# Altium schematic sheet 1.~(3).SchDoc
size 420 x 297 mm
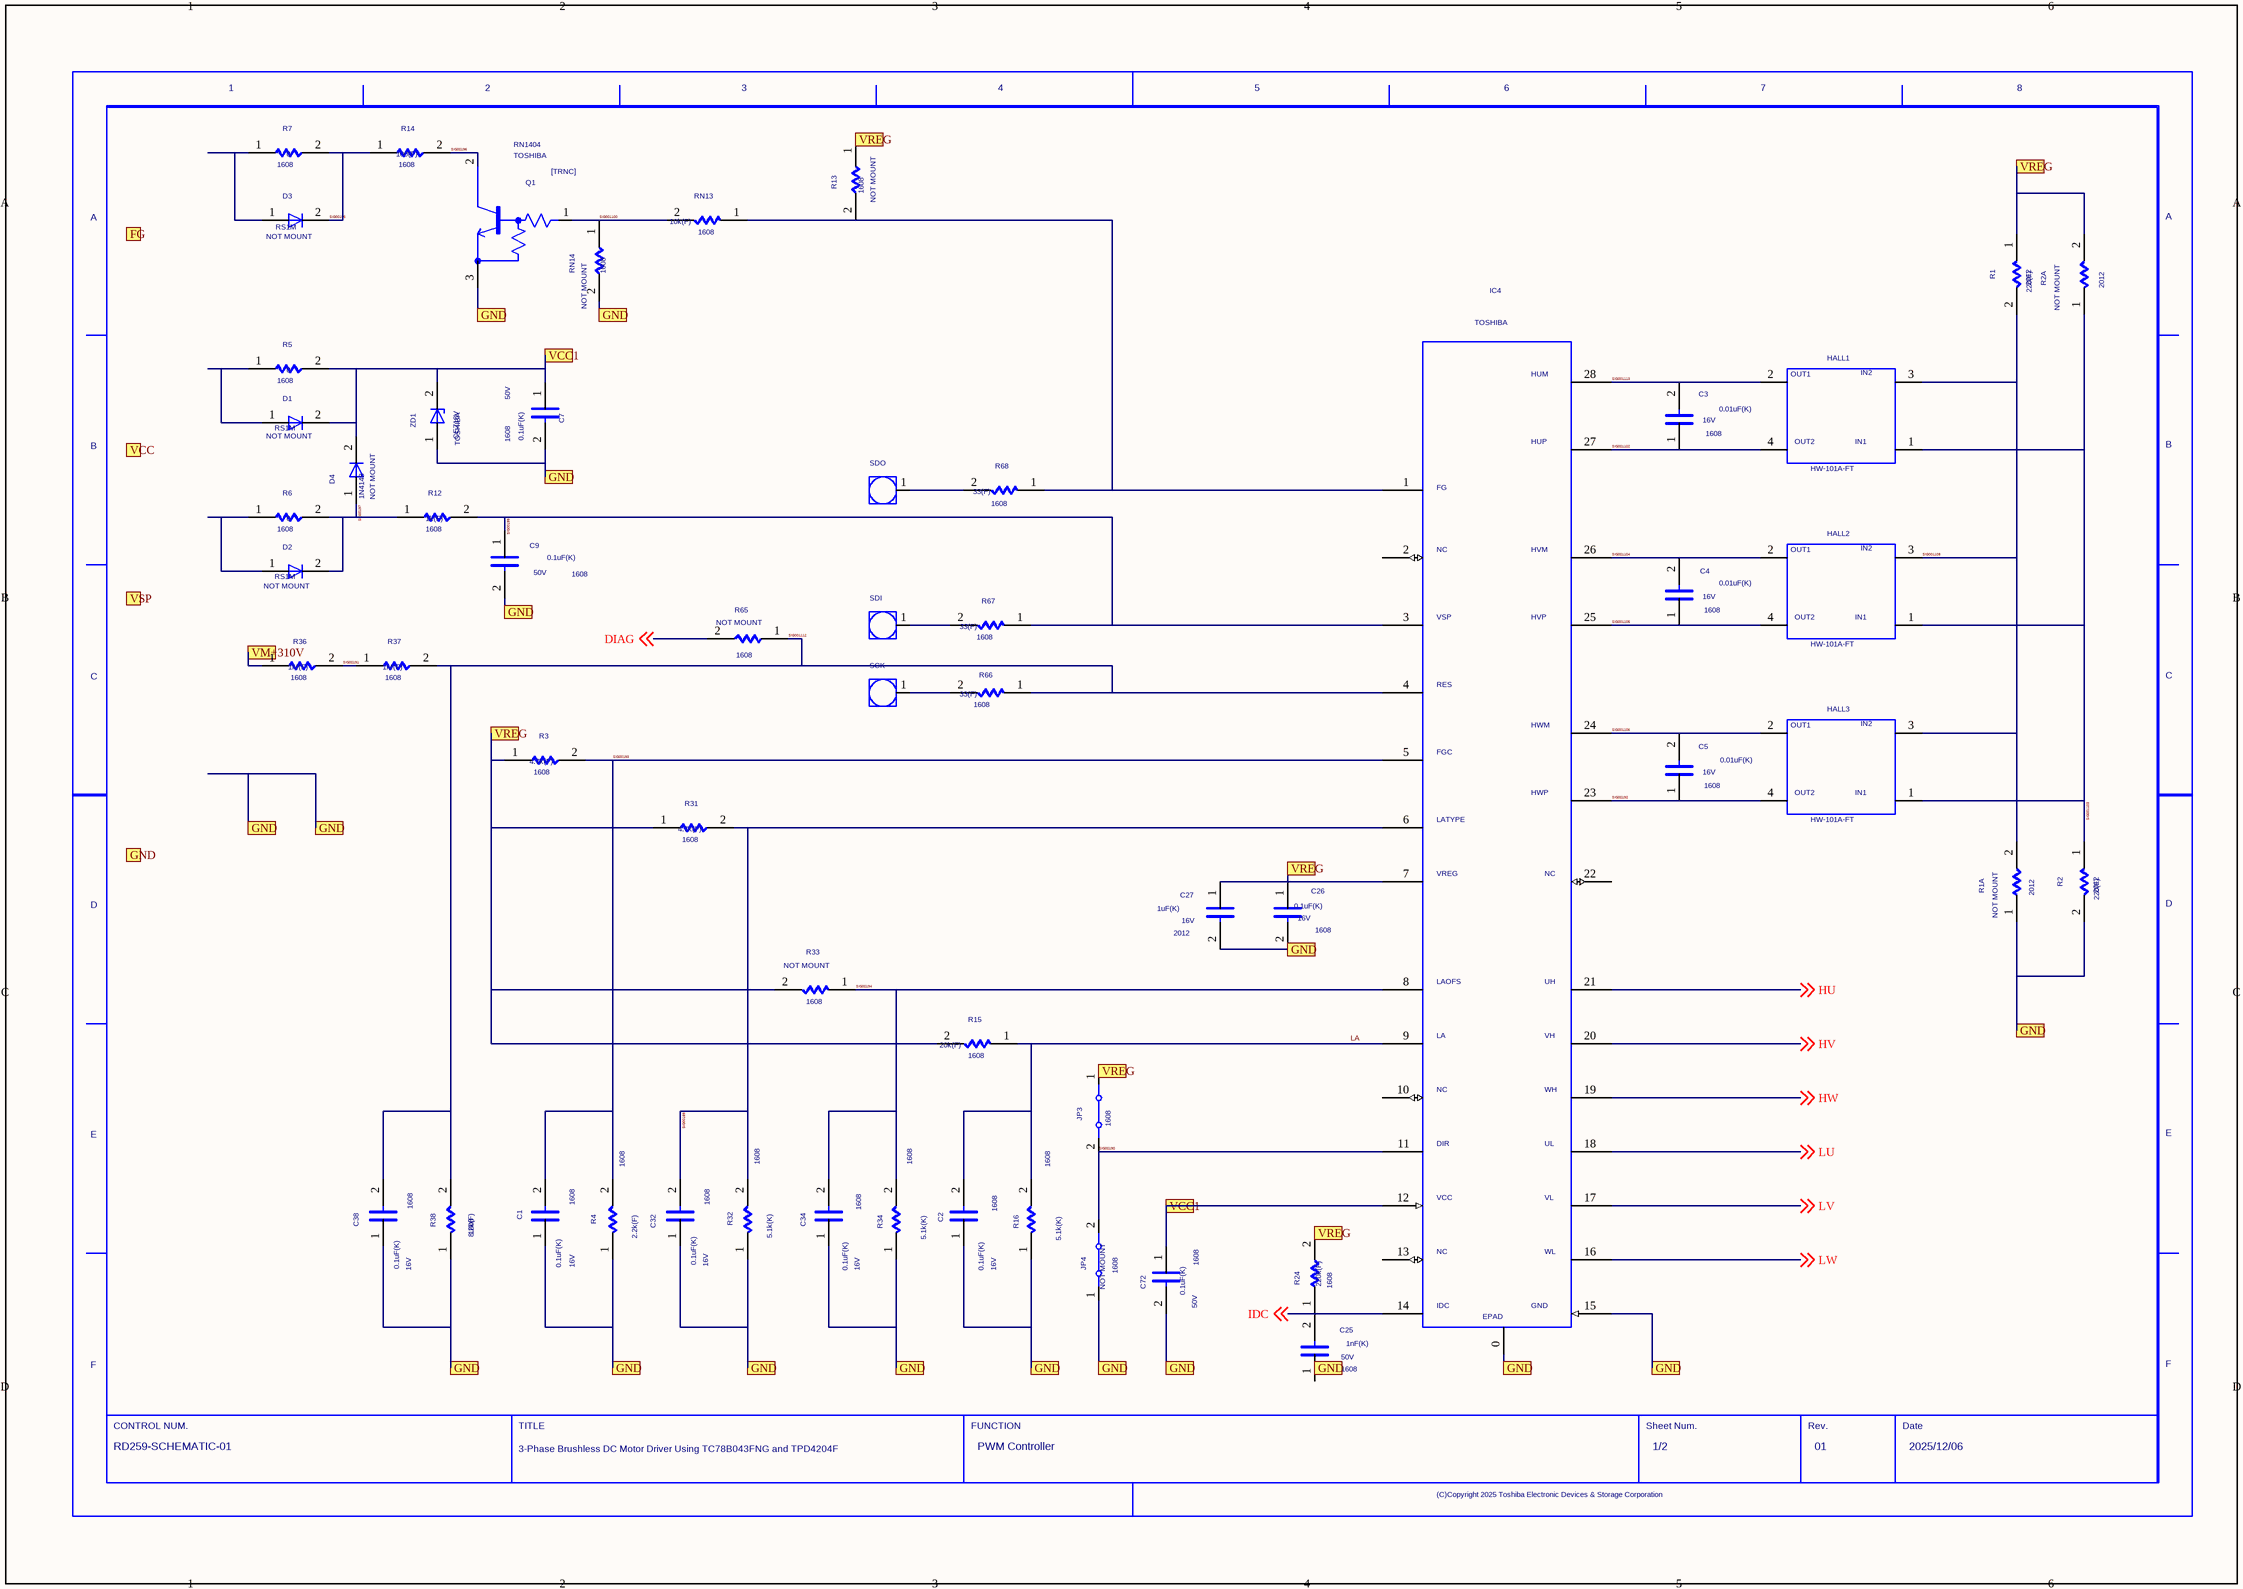
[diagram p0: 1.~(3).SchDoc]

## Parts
C1  VAL1: 0.1uF(K)  VAL2: 16V  SIZECODESMD: 1608  (hidden comment: C)
C2  VAL1: 0.1uF(K)  VAL2: 16V  SIZECODESMD: 1608  (hidden comment: C)
C3  VAL1: 0.01uF(K)  VAL2: 16V  SIZECODESMD: 1608  (hidden comment: C)
C4  VAL1: 0.01uF(K)  VAL2: 16V  SIZECODESMD: 1608  (hidden comment: C)
C5  VAL1: 0.01uF(K)  VAL2: 16V  SIZECODESMD: 1608  (hidden comment: C)
C7  VAL1: 0.1uF(K)  VAL2: 50V  SIZECODESMD: 1608  (hidden comment: C)
C9  VAL1: 0.1uF(K)  VAL2: 50V  SIZECODESMD: 1608  (hidden comment: C)
C25  VAL1: 1nF(K)  VAL2: 50V  SIZECODESMD: 1608  (hidden comment: C)
C26  VAL1: 0.1uF(K)  VAL2: 16V  SIZECODESMD: 1608  (hidden comment: C)
C27  VAL1: 1uF(K)  VAL2: 16V  SIZECODESMD: 2012  (hidden comment: C)
C32  VAL1: 0.1uF(K)  VAL2: 16V  SIZECODESMD: 1608  (hidden comment: C)
C34  VAL1: 0.1uF(K)  VAL2: 16V  SIZECODESMD: 1608  (hidden comment: C)
C38  VAL1: 0.1uF(K)  VAL2: 16V  SIZECODESMD: 1608  (hidden comment: C)
C72  VAL1: 0.1uF(K)  VAL2: 50V  SIZECODESMD: 1608  (hidden comment: C)
D1  VAL3: RS1M  NOTMNT: NOT MOUNT  (hidden comment: D)
D2  VAL3: RS1M  NOTMNT: NOT MOUNT  (hidden comment: D)
D3  NOTMNT: NOT MOUNT  VAL3: RS1M  (hidden comment: D)
D4  NOTMNT: NOT MOUNT  VAL3: 1N4148  (hidden comment: D)
HALL1  HW-101A-FT
HALL2  HW-101A-FT
HALL3  HW-101A-FT
IC4  USERCOMPTEXT3: TOSHIBA  (hidden comment: TC78B043FNG)
JP3  SIZECODESMD: 1608  (hidden comment: JP)
JP4  NOTMNT: NOT MOUNT  SIZECODESMD: 1608  (hidden comment: JP)
Q1  USERCOMPTEXT3: TOSHIBA  VAL3: RN1404  (hidden comment: TRNC)
R1  VAL1: 220(F)  SIZECODESMD: 2012  (hidden comment: R)
R1A  NOTMNT: NOT MOUNT  SIZECODESMD: 2012  (hidden comment: R)
R2  VAL1: 220(F)  SIZECODESMD: 2012  (hidden comment: R)
R2A  NOTMNT: NOT MOUNT  SIZECODESMD: 2012  (hidden comment: R)
R3  VAL1: 4.7k(F)  SIZECODESMD: 1608  (hidden comment: R)
R4  VAL1: 2.2k(F)  SIZECODESMD: 1608  (hidden comment: R)
R5  VAL1: 0  SIZECODESMD: 1608  (hidden comment: R)
R6  VAL1: 0  SIZECODESMD: 1608  (hidden comment: R)
R7  VAL1: 0  SIZECODESMD: 1608  (hidden comment: R)
R12  VAL1: 1k(F)  SIZECODESMD: 1608  (hidden comment: R)
R13  NOTMNT: NOT MOUNT  SIZECODESMD: 1608  (hidden comment: R)
R14  VAL1: 100(F)  SIZECODESMD: 1608  (hidden comment: R)
R15  VAL1: 20k(F)  SIZECODESMD: 1608  (hidden comment: R)
R16  VAL1: 5.1k(K)  SIZECODESMD: 1608  (hidden comment: R)
R24  VAL1: 220k(F)  SIZECODESMD: 1608  (hidden comment: R)
R31  VAL1: 4.7k(F)  SIZECODESMD: 1608  (hidden comment: R)
R32  VAL1: 5.1k(K)  SIZECODESMD: 1608  (hidden comment: R)
R33  NOTMNT: NOT MOUNT  SIZECODESMD: 1608  (hidden comment: R)
R34  VAL1: 5.1k(K)  SIZECODESMD: 1608  (hidden comment: R)
R36  VAL1: 1M(F)  SIZECODESMD: 1608  (hidden comment: R)
R37  VAL1: 1M(F)  SIZECODESMD: 1608  (hidden comment: R)
R38  VAL1: 8.2k(F)  SIZECODESMD: 1608  (hidden comment: R)
R65  NOTMNT: NOT MOUNT  SIZECODESMD: 1608  (hidden comment: R)
R66  VAL1: 33(F)  SIZECODESMD: 1608  (hidden comment: R)
R67  VAL1: 33(F)  SIZECODESMD: 1608  (hidden comment: R)
R68  VAL1: 33(F)  SIZECODESMD: 1608  (hidden comment: R)
RN13  VAL1: 10k(F)  SIZECODESMD: 1608  (hidden comment: R)
RN14  NOTMNT: NOT MOUNT  SIZECODESMD: 1608  (hidden comment: R)
SCK  PAD_FOR_BLDCS50  (value not drawn)
SDI  PAD_FOR_BLDCS50  (value not drawn)
SDO  PAD_FOR_BLDCS50  (value not drawn)
U?  DATE: 2025/12/06  DRAWINGNUMBER: RD259-SCHEMATIC-01  TITLE: 3-Phase Brushless DC Motor Driver / Using TC78B043FNG and TPD4204F  FUNCTION: PWM Controller  SHEETNUMBER: 1/2  REVISION: 01  (hidden comment: WAKU_DEF100)
ZD1  USERCOMPTEXT3: TOSHIBA  VAL3: CEZ18V  (hidden comment: ZD)

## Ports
FG, GND, VCC, VCC1, VM+310V, VREG, VSP

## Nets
DIAG: R65.2 ; off-sheet DIAG
FGOUT: IC4.1 R13.2 R68.1 RN13.1
GND: C1.1 C2.1 C7.2 C9.2 C25.1 C26.2 C27.2 C32.1 C34.1 C38.1 C72.2 IC4.0 IC4.15 JP4.1 Q1.3(E) R1A.1 R2.2 R4.1 R16.1 R32.1 R34.1 R38.1 RN14.2 ZD1.1(A) ; port GND
HU: IC4.21 ; off-sheet HU
HV: IC4.20 ; off-sheet HV
HW: IC4.19 ; off-sheet HW
IDC: C25.2 IC4.14 R24.1 ; off-sheet IDC
LA: C2.2 IC4.9 R15.1 R16.2
LU: IC4.18 ; off-sheet LU
LV: IC4.17 ; off-sheet LV
LW: IC4.16 ; off-sheet LW
SCK: R66.2 SCK.1
SDI: R67.2 SDI.1
SIG00189: C32.2 IC4.6 R31.2 R32.2
SIG00190: IC4.11 JP3.2 JP4.2
SIG00191: R36.2 R37.1
SIG00192: C5.1 HALL3.4 IC4.23
SIG00193: C1.2 IC4.5 R3.2 R4.2
SIG00194: C34.2 IC4.8 R33.1 R34.2
SIG00195: D3.2(C) R7.2 R14.1
SIG00196: Q1.2(C) R14.2
SIG00197: D2.2(C) D4.1(A) R6.2 R12.1
SIG00198: R68.2 SDO.1
SIG00199: C9.1 IC4.3 R12.2 R67.1
SIG001100: Q1.1(B) RN13.2 RN14.1
SIG001102: C3.1 HALL1.4 IC4.27
SIG001103: HALL1.1 HALL2.1 HALL3.1 R2.1 R2A.1
SIG001104: C4.2 HALL2.2 IC4.26
SIG001105: C4.1 HALL2.4 IC4.25
SIG001106: C5.2 HALL3.2 IC4.24
SIG001108: HALL1.3 HALL2.3 HALL3.3 R1.2 R1A.2
SIG001112: C38.2 IC4.4 R37.2 R38.2 R65.1 R66.1
SIG001113: C3.2 HALL1.2 IC4.28
VCC1: C7.1 C72.1 D1.2(C) D4.2(C) IC4.12 R5.2 ZD1.2(C) ; port VCC1
VM+310V: R36.1 ; port VM+310V
VREG: C26.1 C27.1 IC4.7 JP3.1 R1.1 R2A.2 R3.1 R13.1 R15.2 R24.2 R31.1 R33.2 ; port VREG
NetD1_1: D1.1(A) R5.1
NetD2_1: D2.1(A) R6.1
NetD3_1: D3.1(A) R7.1

Not connected (* = marked no-connect by the designer): IC4 2 10 13 22

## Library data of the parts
C1-C5 C7 C9 C25-C27 C32 C34 C38 C72 = C_Dup1: OriginalSymbolOrigin: (2540,7620); SAVECOUNT: 0
D1-D4 = D: SAVEAREA0: -225,-91,12804,7836; SAVECOUNT: 3; TIME: 14:49:55; UPDATEUSER: 19870035; UPDATETIME: 14:20:16; OriginalSymbolOrigin: (5080,5080)
HALL1-HALL3 = HW-101A-FT: SAVEAREA0: -12224,-318,37706,25614; TIME: 11:47:14; UPDATEUSER: t5459927; UPDATETIME: 12:34:57; SAVECOUNT: 11; OriginalSymbolOrigin: (5080,17780)
IC4 = TC78B043FNG: SAVEAREA0: -18325,-397,56528,38480; SAVECOUNT: 26; TIME: 12:23:18; UPDATEUSER: t5459927; UPDATETIME: 08:57:33; OriginalSymbolOrigin: (7620,190500)
JP3 JP4 = JP: OriginalSymbolOrigin: (2540,5080); SAVECOUNT: 0
Q1 = TRNC: OriginalSymbolOrigin: (2540,22860); SAVECOUNT: 0
R1-R4 R12 R14-R16 R24 R31 R32 R34 R36-R38 R66-R68 RN13 = R_Dup1: VAL2: 100mW; OriginalSymbolOrigin: (5080,5080); SAVECOUNT: 0
R1A R2A R33 = R_Dup1: OriginalSymbolOrigin: (5080,5080); SAVECOUNT: 0
R5-R7 = R_Dup1: OriginalSymbolOrigin: (5080,5080)
R13 R65 RN14 = R: OriginalSymbolOrigin: (5080,5080); SAVECOUNT: 0
SCK SDI SDO = PAD_FOR_BLDCS50: SAVEAREA0: -12224,-318,37706,25614; TIME: 11:47:14; UPDATEUSER: t5459927; UPDATETIME: 16:31:56; SAVECOUNT: 8; OriginalSymbolOrigin: (7620,17780); DEVICE: PAD
U? = WAKU_DEF100: SAVEAREA0: -63393,-16950,474261,314592; TIME: 14:30:25; UPDATEUSER: t5459927; UPDATETIME: 15:25:21; SAVECOUNT: 3; OriginalSymbolOrigin: (10160,284480); SHTSAVECOUNT: 4
ZD1 = ZD: SAVEAREA0: -4630,-153,17114,13055; TIME: 14:49:55; UPDATEUSER: fukuda-y; UPDATETIME: 08:18:42; SAVECOUNT: 6; OriginalSymbolOrigin: (5080,5080)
